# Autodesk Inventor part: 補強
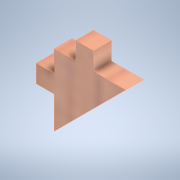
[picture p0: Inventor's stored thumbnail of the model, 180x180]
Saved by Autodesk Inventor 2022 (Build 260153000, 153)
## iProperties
Created: 2024-12
Part Number: 補強
Material: 木 (オーク)
Document SubType Name: Modeling
Designer: shimizu
Density: 0.76 g/cm^3
Appearance: ホワイト オーク材 - ナチュラル 標準の光沢
Author: shimizu
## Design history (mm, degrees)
sketch "スケッチ2"
  geometry: L1 (-5.085, 3.641)-(4.915, 3.641); L2 (4.915, 3.641)-(4.915, -6.359); L3 (4.915, -6.359)-(-5.085, -6.359); L4 (-5.085, -6.359)-(-5.085, 3.641); L5 (4.915, 3.641)-(-5.085, -6.359); L6 (-2.085, 3.641)-(0.415, 3.641); L7 (0.415, 3.641)-(0.415, 6.141); L8 (0.415, 6.141)-(-2.085, 6.141); L9 (-2.085, 6.141)-(-2.085, 3.641); L10 (-5.085, 0.641)-(-7.585, 0.641); L11 (-7.585, 0.641)-(-7.585, -1.859); L12 (-7.585, -1.859)-(-5.085, -1.859); L13 (-5.085, -1.859)-(-5.085, 0.641); 3 further points
  constraints: 26 end point, 6 parallel, 3 horizontal, 3 perpendicular, 2 point on line
  dimensions: "d13" = 10 distance of L1.start L1.end; "d14" = 10 distance of L3.end L1.start; "d15" = 2.5 distance of L7.end L8.end; "d16" = 2.5 distance of L6.end L7.end; "d17" = 2.5 distance of L10.start L10.end; "d18" = 2.5 distance of L10.end L11.end; "d19" = 3 distance between parallel lines of L9 L4; "d20" = 3 distance between parallel lines of L10 L1
extrude "押し出し2" new body sketch "スケッチ2" distance "d21" = 2.5; taper "d22" = 0 deg
node "ソリッド2"
other parameters: "d0" = 8
